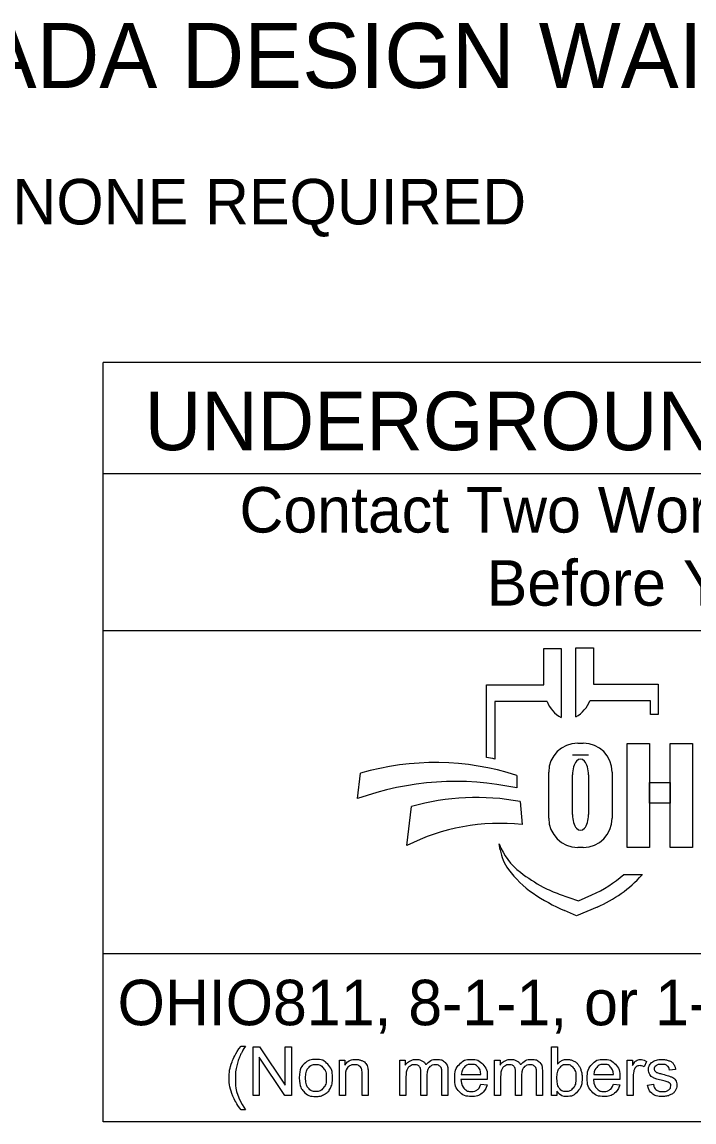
# Model space of a CAD drawing. Extents: x -7.3 to 34, y 0 to 22.
# Drawn here: x 2.128 to 4.196, y 2.143 to 5.529 of the extents above; entities that cross this region are included whole.
import ezdxf

# ---------------------------------------------------------------- set-up
doc = ezdxf.new("R2010")
doc.units = 0
doc.layers.add('SH_Data', color=7, linetype='Continuous')
doc.layers.add('SH_Text', color=7, linetype='Continuous')

msp = doc.modelspace()

# ---------------------------------------------------------------- linework, layer by layer
at = {"layer": 'SH_Data'}
for p, q in [((2.3775, 2.1428), (2.3775, 4.4803)), ((6.6275, 4.4803), (2.3775, 4.4803)), ((2.3775, 4.1387), (6.6275, 4.1387)), ((2.3775, 3.6553), (6.6275, 3.6553)), ((6.6275, 2.6607), (2.3775, 2.6607)), ((6.6275, 2.1428), (2.3775, 2.1428))]:
    msp.add_line(p, q, dxfattribs=at)
at = {"layer": 'SH_Text'}
for p, q in [((3.7335, 3.4883), (3.7335, 3.5998)), ((3.7335, 3.5998), (3.7872, 3.5998)), ((3.7872, 3.5998), (3.7872, 3.3877)), ((3.8329, 3.39), (3.8329, 3.6021)), ((3.8329, 3.6021), (3.8865, 3.6021)), ((3.8865, 3.6021), (3.8865, 3.4906)), ((3.5576, 3.2644), (3.5576, 3.4883)), ((3.5576, 3.4883), (3.7335, 3.4883)), ((3.8865, 3.4906), (4.0857, 3.4906)), ((4.0857, 3.4906), (4.0857, 3.3968)), ((3.5828, 3.4369), (3.5828, 3.26)), ((3.7439, 3.4369), (3.5828, 3.4369)), ((4.0625, 3.4392), (3.8761, 3.4392)), ((4.0625, 3.3968), (4.0625, 3.4392)), ((4.0857, 3.3968), (4.0625, 3.3968)), ((3.8385, 3.3091), (3.8551, 3.3091)), ((3.8718, 3.2721), (3.822, 3.2721)), ((3.7491, 3.0776), (3.7491, 3.2196)), ((3.9445, 3.2196), (3.9445, 3.0776)), ((3.1602, 3.1381), (3.1696, 3.2162)), ((3.6509, 3.2097), (3.6509, 3.1709)), ((3.822, 3.089), (3.822, 3.2114)), ((3.8718, 3.2114), (3.8718, 3.089)), ((3.6608, 3.1291), (3.6671, 3.0582)), ((3.312, 2.9936), (3.3267, 3.1137)), ((3.5997, 2.9807), (3.5967, 2.9986)), ((3.8551, 2.9882), (3.8385, 2.9882)), ((3.98, 2.9048), (4.0375, 2.9048)), ((3.7816, 2.8444), (3.841, 2.8239)), ((3.841, 2.8239), (3.8821, 2.8417)), ((3.835, 2.7769), (3.7976, 2.7934)), ((3.8983, 2.8044), (3.835, 2.7769))]:
    msp.add_line(p, q, dxfattribs=at)
for points in [[(3.991, 3.3081), (4.0589, 3.3081), (4.0589, 2.9881), (3.991, 2.9881)], [(4.1231, 3.3081), (4.1911, 3.3081), (4.1911, 2.9881), (4.1231, 2.9881)], [(4.0589, 3.1882), (4.1231, 3.1882), (4.1231, 3.1242), (4.0589, 3.1242)]]:
    msp.add_lwpolyline(points, close=True, dxfattribs=at)
for points in [[(2.8021, 2.3766), (2.8153, 2.3766)], [(2.8389, 2.2239), (2.8389, 2.3741), (2.8592, 2.3741), (2.9382, 2.2561), (2.9382, 2.3741), (2.9572, 2.3741), (2.9572, 2.2239), (2.9369, 2.2239), (2.8579, 2.3419), (2.8579, 2.2239), (2.8389, 2.2239)], [(3.7743, 2.2239), (3.7573, 2.2239), (3.7573, 2.3741), (3.7757, 2.3741), (3.7757, 2.3206)], [(3.1048, 2.2239), (3.1048, 2.3328), (3.1214, 2.3328), (3.1214, 2.3173)], [(3.2912, 2.2239), (3.2912, 2.3328), (3.3077, 2.3328), (3.3077, 2.3174)], [(3.5826, 2.2239), (3.5826, 2.3328), (3.5991, 2.3328), (3.5991, 2.3174)], [(3.9904, 2.2239), (3.9904, 2.3328), (4.007, 2.3328), (4.007, 2.3163)], [(4.0495, 2.3293), (4.043, 2.3122)], [(4.1394, 2.3046), (4.1213, 2.3022)], [(3.1233, 2.2833), (3.1233, 2.2239), (3.1048, 2.2239)], [(3.1932, 2.2908), (3.1932, 2.2239), (3.1748, 2.2239), (3.1748, 2.2901)], [(3.3097, 2.2803), (3.3097, 2.2239), (3.2912, 2.2239)], [(3.3743, 2.2871), (3.3743, 2.2239), (3.3559, 2.2239), (3.3559, 2.2946)], [(3.4388, 2.2986), (3.4388, 2.2239), (3.4203, 2.2239), (3.4203, 2.2924)], [(3.56, 2.2736), (3.4788, 2.2736)], [(3.4799, 2.2887), (3.5406, 2.2887)], [(3.601, 2.2803), (3.601, 2.2239), (3.5826, 2.2239)], [(3.6657, 2.2871), (3.6657, 2.2239), (3.6473, 2.2239), (3.6473, 2.2946)], [(3.7301, 2.2986), (3.7301, 2.2239), (3.7117, 2.2239), (3.7117, 2.2924)], [(3.968, 2.2736), (3.8868, 2.2736)], [(3.8879, 2.2887), (3.9486, 2.2887)], [(4.0088, 2.2809), (4.0088, 2.2239), (3.9904, 2.2239)], [(3.5404, 2.2591), (3.5595, 2.2567)], [(3.7743, 2.2375), (3.7743, 2.2239)], [(3.9484, 2.2591), (3.9675, 2.2567)], [(4.053, 2.2564), (4.0712, 2.2593)], [(2.8153, 2.1798), (2.8021, 2.1798)]]:
    msp.add_lwpolyline(points, dxfattribs=at)
for centre, radius, start, end in [((3.8353, 3.4736), 0.0985, 201.9296, 240.7469), ((3.7847, 3.476), 0.0985, 299.2531, 338.0704), ((3.8385, 3.2196), 0.0895, 90, 180), ((3.8551, 3.2196), 0.0895, 0, 90), ((3.4295, 2.4554), 0.8191, 79.2074, 81.0007), ((3.3997, 2.4302), 0.8191, 72.1402, 106.3144), ((3.4628, 2.2991), 0.8919, 77.8238, 109.8274), ((3.5267, 2.4094), 0.7322, 79.44, 105.8467), ((3.5987, 2.4262), 0.6357, 83.8248, 116.8021), ((3.8385, 3.0776), 0.0895, 180, 270), ((3.8551, 3.0776), 0.0895, 270, 0), ((3.7841, 3.0707), 0.2008, 201.0457, 232.5314), ((3.741, 3.0048), 0.1433, 189.6817, 216.0884), ((3.8747, 3.1022), 0.3088, 216.0884, 235.7167), ((3.9766, 3.3219), 0.5173, 232.5314, 241.794), ((3.7387, 3.1722), 0.3602, 293.4582, 312.0712), ((3.7387, 3.1722), 0.401, 293.4582, 317.8286), ((4.0412, 3.3465), 0.6044, 235.7167, 246.2325), ((3.8914, 3.1631), 0.3371, 241.794, 250.9821)]:
    msp.add_arc(centre, radius, start, end, dxfattribs=at)
for centre, start_param, end_param in [((3.8469, 3.2114), 4.712389, 7.853982), ((3.8469, 3.089), 1.570796, 4.712389)]:
    msp.add_ellipse(centre, major_axis=(0, 0.0484), ratio=0.514403, start_param=start_param, end_param=end_param, dxfattribs=at)
for points in [[(2.8021, 2.1798), (2.7869, 2.199), (2.7763, 2.2248), (2.7657, 2.2506), (2.7657, 2.2783), (2.7657, 2.3026), (2.7736, 2.325), (2.7829, 2.3509), (2.8021, 2.3766)], [(2.8153, 2.3766), (2.8029, 2.3553), (2.7989, 2.3462), (2.7927, 2.332), (2.7891, 2.3167), (2.7847, 2.2975), (2.7847, 2.2782), (2.7847, 2.2289), (2.8153, 2.1798)], [(2.9814, 2.2783), (2.9814, 2.3085), (2.9981, 2.3231), (3.0122, 2.3352), (3.0323, 2.3352), (3.0547, 2.3352), (3.069, 2.3205), (3.0832, 2.3058), (3.0832, 2.2799), (3.0832, 2.2589), (3.0769, 2.2469), (3.0706, 2.2348), (3.0586, 2.2282), (3.0466, 2.2215), (3.0323, 2.2215), (3.0095, 2.2215), (2.9954, 2.2362), (2.9814, 2.2508), (2.9814, 2.2783)], [(3.0003, 2.2783), (3.0003, 2.2574), (3.0094, 2.247), (3.0185, 2.2366), (3.0323, 2.2366), (3.046, 2.2366), (3.0551, 2.2471), (3.0642, 2.2575), (3.0642, 2.279), (3.0642, 2.2991), (3.0551, 2.3095), (3.0459, 2.3199), (3.0323, 2.3199), (3.0185, 2.3199), (3.0094, 2.3096), (3.0003, 2.2992), (3.0003, 2.2783)], [(3.1214, 2.3173), (3.1334, 2.3352), (3.156, 2.3352), (3.1659, 2.3352), (3.1741, 2.3316), (3.1823, 2.3281), (3.1864, 2.3224), (3.1905, 2.3166), (3.1922, 2.3087), (3.1932, 2.3036), (3.1932, 2.2908)], [(3.1748, 2.2901), (3.1748, 2.3013), (3.1726, 2.3069), (3.1705, 2.3125), (3.165, 2.3158), (3.1595, 2.3191), (3.1521, 2.3191), (3.1404, 2.3191), (3.1318, 2.3117), (3.1233, 2.3042), (3.1233, 2.2833)], [(3.3077, 2.3174), (3.3128, 2.3254), (3.3214, 2.3303), (3.3299, 2.3352), (3.3407, 2.3352), (3.3528, 2.3352), (3.3606, 2.3301), (3.3683, 2.3251), (3.3715, 2.3161), (3.3844, 2.3352), (3.4051, 2.3352), (3.4213, 2.3352), (3.43, 2.3262), (3.4388, 2.3172), (3.4388, 2.2986)], [(3.3559, 2.2946), (3.3559, 2.3069), (3.3514, 2.313), (3.3469, 2.3191), (3.3366, 2.3191), (3.3288, 2.3191), (3.3222, 2.315), (3.3156, 2.311), (3.3126, 2.3031), (3.3097, 2.2952), (3.3097, 2.2803)], [(3.4203, 2.2924), (3.4203, 2.3035), (3.4185, 2.3083), (3.4168, 2.3132), (3.412, 2.3162), (3.4073, 2.3191), (3.401, 2.3191), (3.3895, 2.3191), (3.3819, 2.3115), (3.3743, 2.3039), (3.3743, 2.2871)], [(3.5595, 2.2567), (3.555, 2.24), (3.5428, 2.2307), (3.5306, 2.2215), (3.5117, 2.2215), (3.4878, 2.2215), (3.4738, 2.2362), (3.4598, 2.2509), (3.4598, 2.2774), (3.4598, 2.3049), (3.474, 2.32), (3.4881, 2.3352), (3.5106, 2.3352), (3.5324, 2.3352), (3.5463, 2.3203), (3.5601, 2.3055), (3.5601, 2.2785), (3.5601, 2.2769), (3.56, 2.2736)], [(3.5406, 2.2887), (3.5394, 2.3025), (3.5337, 2.3094), (3.5249, 2.3201), (3.5108, 2.3201), (3.4981, 2.3201), (3.4894, 2.3115), (3.4808, 2.303), (3.4799, 2.2887)], [(3.5991, 2.3174), (3.6042, 2.3254), (3.6127, 2.3303), (3.6212, 2.3352), (3.6321, 2.3352), (3.6442, 2.3352), (3.6519, 2.3301), (3.6597, 2.3251), (3.6628, 2.3161), (3.6758, 2.3352), (3.6965, 2.3352), (3.7127, 2.3352), (3.7214, 2.3262), (3.7301, 2.3172), (3.7301, 2.2986)], [(3.6473, 2.2946), (3.6473, 2.3069), (3.6428, 2.313), (3.6383, 2.3191), (3.628, 2.3191), (3.6202, 2.3191), (3.6136, 2.315), (3.607, 2.311), (3.604, 2.3031), (3.601, 2.2952), (3.601, 2.2803)], [(3.7117, 2.2924), (3.7117, 2.3035), (3.7099, 2.3083), (3.7081, 2.3132), (3.7034, 2.3162), (3.6987, 2.3191), (3.6923, 2.3191), (3.6809, 2.3191), (3.6733, 2.3115), (3.6657, 2.3039), (3.6657, 2.2871)], [(3.7741, 2.2792), (3.7741, 2.2596), (3.7794, 2.2509), (3.7881, 2.2366), (3.8029, 2.2366), (3.815, 2.2366), (3.8238, 2.2471), (3.8326, 2.2576), (3.8326, 2.2784), (3.8326, 2.2998), (3.8241, 2.3099), (3.8157, 2.3201), (3.8038, 2.3201), (3.7917, 2.3201), (3.7829, 2.3096), (3.7741, 2.299), (3.7741, 2.2792)], [(3.7757, 2.3206), (3.7874, 2.3352), (3.8055, 2.3352), (3.8155, 2.3352), (3.8245, 2.3311), (3.8335, 2.3271), (3.8392, 2.3198), (3.845, 2.3124), (3.8483, 2.3021), (3.8516, 2.2918), (3.8516, 2.28), (3.8516, 2.252), (3.8378, 2.2368), (3.8239, 2.2215), (3.8046, 2.2215), (3.7853, 2.2215), (3.7743, 2.2375)], [(3.9675, 2.2567), (3.963, 2.24), (3.9508, 2.2307), (3.9386, 2.2215), (3.9196, 2.2215), (3.8958, 2.2215), (3.8818, 2.2362), (3.8678, 2.2509), (3.8678, 2.2774), (3.8678, 2.3049), (3.882, 2.32), (3.8961, 2.3352), (3.9186, 2.3352), (3.9404, 2.3352), (3.9543, 2.3203), (3.9681, 2.3055), (3.9681, 2.2785), (3.9681, 2.2769), (3.968, 2.2736)], [(3.9486, 2.2887), (3.9474, 2.3025), (3.9417, 2.3094), (3.9328, 2.3201), (3.9188, 2.3201), (3.9061, 2.3201), (3.8974, 2.3115), (3.8888, 2.303), (3.8879, 2.2887)], [(4.007, 2.3163), (4.0133, 2.3278), (4.0187, 2.3315), (4.0241, 2.3352), (4.0305, 2.3352), (4.0398, 2.3352), (4.0495, 2.3293)], [(4.043, 2.3122), (4.0363, 2.3162), (4.0295, 2.3162), (4.0235, 2.3162), (4.0187, 2.3125), (4.0139, 2.3089), (4.0119, 2.3024), (4.0088, 2.2926), (4.0088, 2.2809)], [(4.1213, 2.3022), (4.1201, 2.3106), (4.1142, 2.3153), (4.1083, 2.3201), (4.0975, 2.3201), (4.0848, 2.3201), (4.0794, 2.3159), (4.0739, 2.3116), (4.0739, 2.306), (4.0739, 2.3024), (4.0762, 2.2995), (4.0785, 2.2966), (4.0833, 2.2946), (4.086, 2.2936), (4.0996, 2.2899), (4.1192, 2.2847), (4.1269, 2.2813), (4.1347, 2.278), (4.1391, 2.2717), (4.1435, 2.2653), (4.1435, 2.2559), (4.1435, 2.2467), (4.1381, 2.2386), (4.1327, 2.2304), (4.1226, 2.226), (4.1124, 2.2215), (4.0996, 2.2215), (4.0784, 2.2215), (4.0672, 2.2303), (4.0561, 2.2391), (4.053, 2.2564)], [(4.0712, 2.2593), (4.0727, 2.2483), (4.0798, 2.2425), (4.0868, 2.2366), (4.0995, 2.2366), (4.1122, 2.2366), (4.1184, 2.2418), (4.1245, 2.247), (4.1245, 2.254), (4.1245, 2.2602), (4.1191, 2.2638), (4.1153, 2.2663), (4.1002, 2.2701), (4.0799, 2.2752), (4.072, 2.2789), (4.0642, 2.2827), (4.0601, 2.2893), (4.0561, 2.2959), (4.0561, 2.3038), (4.0561, 2.3111), (4.0594, 2.3173), (4.0628, 2.3235), (4.0685, 2.3276), (4.0728, 2.3308), (4.0803, 2.333), (4.0877, 2.3352), (4.0962, 2.3352), (4.109, 2.3352), (4.1187, 2.3315), (4.1284, 2.3278), (4.133, 2.3215), (4.1377, 2.3152), (4.1394, 2.3046)], [(3.4788, 2.2736), (3.4799, 2.2557), (3.489, 2.2462), (3.4981, 2.2366), (3.5117, 2.2366), (3.5219, 2.2366), (3.5291, 2.242), (3.5362, 2.2473), (3.5404, 2.2591)], [(3.8868, 2.2736), (3.8879, 2.2557), (3.897, 2.2462), (3.9061, 2.2366), (3.9197, 2.2366), (3.9299, 2.2366), (3.937, 2.242), (3.9442, 2.2473), (3.9484, 2.2591)]]:
    msp.add_open_spline(points, degree=3, dxfattribs=at)

# ---------------------------------------------------------------- texts
for s, height, p in [('ADA DESIGN WAIVERS', 0.2, (1.9944, 5.3256)), ('  NONE REQUIRED                          ', 0.14, (1.9944, 4.9056)), ('UNDERGROUND UTILITIES', 0.18, (2.5057, 4.2106)), ('Contact Two Working Days', 0.14, (2.7972, 3.9571)), ('Before You Dig', 0.14, (3.5583, 3.7321)), ('OHIO811, 8-1-1, or 1-800-362-2764', 0.14, (2.422, 2.4406))]:
    msp.add_text(s, height=height, dxfattribs=at).set_placement(p)

doc.saveas('drawing.dxf')
